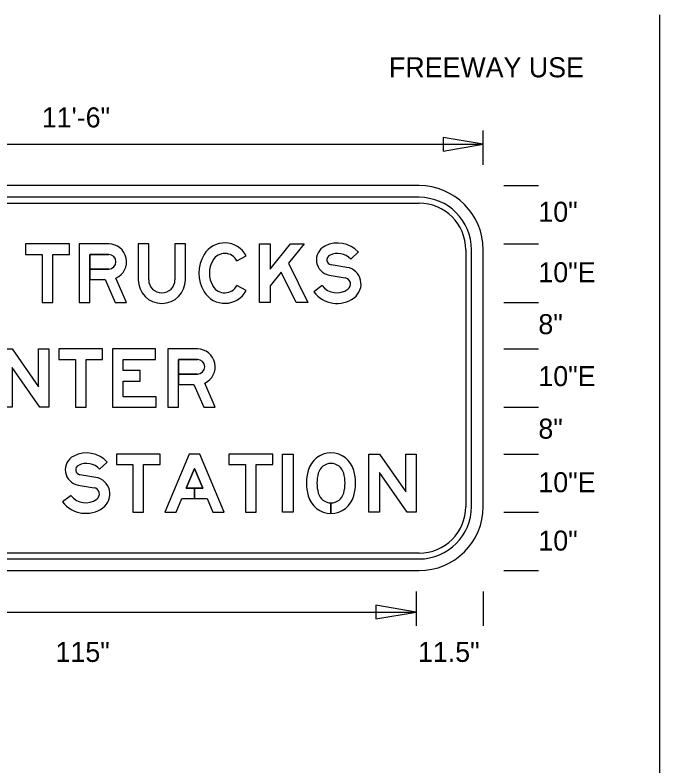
# Model space of a CAD drawing. Extents: x 0 to 770, y 0 to 495.
# Drawn here: x 80.1 to 192.8, y 363.9 to 495 of the extents above; entities that cross this region are included whole.
import ezdxf

# ---------------------------------------------------------------- set-up
doc = ezdxf.new("R2010")
doc.units = 0
for name, color, linetype in [('Dimension', 7, 'Continuous'), ('GSBWFill', 7, 'Continuous'), ('GSColorFill', 7, 'Continuous'), ('GSDims', 7, 'Continuous'), ('GSOutline', 7, 'Continuous'), ('SheetLines_dp', 7, 'Continuous'), ('TextStructures', 7, 'Continuous')]:
    doc.layers.add(name, color=color, linetype=linetype)

msp = doc.modelspace()

# ---------------------------------------------------------------- linework, layer by layer
at = {"layer": 'Dimension'}
for points in [[(161.91, 472.41), (154.9, 473.59), (154.9, 471.22)], [(150.19, 390.68), (143.17, 391.87), (143.17, 389.49)]]:
    msp.add_lwpolyline(points, close=True, dxfattribs=at)
at = {"layer": 'GSBWFill'}
for p, q in [((150.7, 465.18), (32.46, 465.18)), ((150.7, 463.14), (32.46, 463.14)), ((32.46, 462.12), (150.7, 462.12)), ((108.04, 454.99), (108.04, 448.74)), ((138.76, 452.34), (140.1, 453.59)), ((158.86, 453.97), (158.86, 409.12)), ((159.87, 409.12), (159.87, 453.97)), ((161.91, 409.12), (161.91, 453.97)), ((118.86, 452.06), (120.48, 452.92)), ((138.1, 450.9), (135.32, 451.37)), ((135.01, 449.56), (137.79, 449.09)), ((120.48, 446.86), (118.86, 447.72)), ((118.86, 447.72), (118.86, 447.72)), ((133.76, 447.72), (132.3, 446.6)), ((94.87, 415.64), (96.22, 416.89)), ((94.21, 414.2), (91.44, 414.67)), ((91.13, 412.86), (93.91, 412.39)), ((89.88, 411.03), (88.42, 409.91)), ((135.31, 407.92), (135.31, 409.76)), ((135.31, 409.76), (135.31, 407.92)), ((150.7, 400.96), (32.47, 400.96)), ((32.47, 399.95), (150.7, 399.95)), ((32.46, 397.91), (150.7, 397.91))]:
    msp.add_line(p, q, dxfattribs=at)
for points in [[(81.95, 453.15), (84.85, 453.15), (84.85, 444.79), (86.69, 444.79), (86.69, 453.15), (89.59, 453.15), (89.59, 454.99), (81.95, 454.99)], [(130.62, 454.99), (127.89, 451.62), (131.28, 444.79), (129.23, 444.79), (126.62, 450.06), (124.66, 447.65), (124.66, 444.79), (122.82, 444.79), (122.82, 454.99), (124.66, 454.99), (124.66, 450.56), (128.26, 454.99)], [(86.03, 436.64), (86.03, 426.45), (84.45, 426.45), (79.6, 433.43), (79.6, 426.45), (77.77, 426.45), (77.77, 436.64), (79.61, 436.64), (84.19, 430.03), (84.19, 436.64)], [(87.76, 434.81), (90.66, 434.81), (90.66, 426.45), (92.5, 426.45), (92.5, 434.81), (95.4, 434.81), (95.4, 436.64), (87.76, 436.64)], [(104.78, 428.28), (98.97, 428.28), (98.97, 431.02), (101.98, 431.02), (101.98, 432.86), (98.97, 432.86), (98.97, 434.81), (104.63, 434.81), (104.63, 436.64), (97.14, 436.64), (97.14, 426.45), (104.78, 426.45)], [(97.8, 416.46), (100.7, 416.46), (100.7, 408.1), (102.54, 408.1), (102.54, 416.46), (105.44, 416.46), (105.44, 418.29), (97.8, 418.29)], [(112.89, 412.33), (111.46, 412.33), (111.46, 410.5), (113.66, 410.5), (114.67, 408.1), (116.66, 408.1), (112.38, 418.29), (110.54, 418.29), (106.26, 408.1), (108.25, 408.1), (109.26, 410.5), (111.46, 410.5), (111.46, 412.33), (110.03, 412.33), (111.46, 415.74)], [(117.47, 416.46), (120.38, 416.46), (120.38, 408.1), (122.21, 408.1), (122.21, 416.46), (125.12, 416.46), (125.12, 418.29), (117.47, 418.29)], [(126.85, 408.1), (126.85, 418.29), (128.68, 418.29), (128.68, 408.1)], [(150.19, 418.29), (150.19, 408.1), (148.61, 408.1), (143.77, 415.08), (143.77, 408.1), (141.93, 408.1), (141.93, 418.29), (143.78, 418.29), (148.36, 411.69), (148.36, 418.29)]]:
    msp.add_lwpolyline(points, close=True, dxfattribs=at)
for points in [[(96.47, 454.99), (91.33, 454.99), (91.33, 444.79), (93.16, 444.79), (93.16, 453.15), (96.47, 453.15)], [(103.46, 448.74), (103.46, 454.99), (101.62, 454.99), (101.62, 448.74)], [(109.88, 448.74), (109.88, 454.99), (108.04, 454.99)], [(96.47, 450.6), (93.16, 450.6), (93.16, 448.77)], [(93.16, 448.77), (95.86, 448.77), (97.58, 444.79), (99.58, 444.79), (97.74, 449.04)], [(111.97, 436.64), (106.82, 436.64), (106.82, 426.45), (108.65, 426.45), (108.65, 434.81), (111.97, 434.81)], [(111.97, 432.26), (108.66, 432.26), (108.66, 430.42)], [(108.66, 430.42), (111.36, 430.42), (113.08, 426.45), (115.08, 426.45), (113.24, 430.69)]]:
    msp.add_lwpolyline(points, dxfattribs=at)
for centre, radius, start, end in [((150.7, 453.97), 11.21, 0, 90), ((150.7, 453.97), 9.17, 0, 90), ((150.7, 453.97), 8.15, 0, 90), ((136.48, 450.22), 4.94, 42.8759, 116.9123), ((135.46, 452.22), 2.7, 116.9123, 260.4087), ((135.46, 452.22), 0.866, 116.9123, 260.4087), ((136.48, 450.22), 3.11, 42.8759, 116.9123), ((137.6, 447.98), 2.96, 306.123, 80.4087), ((105.75, 448.74), 4.13, 180, 0), ((105.75, 448.74), 2.29, 180, 0), ((137.6, 447.98), 1.12, 306.123, 80.4087), ((136.34, 449.71), 3.26, 217.5895, 306.123), ((136.34, 449.71), 5.1, 217.5895, 306.123), ((150.7, 409.12), 9.17, 270, 0), ((150.7, 409.12), 8.15, 270, 0), ((150.7, 409.12), 11.21, 270, 0)]:
    msp.add_arc(centre, radius, start, end, dxfattribs=at)
for centre, major_axis, start_param, end_param in [((96.47, 451.88), (0, 3.11), 3.562504, 6.283185), ((116.74, 450.94), (0, 4.23), 5.201543, 7.308565), ((96.47, 451.88), (0, 1.27), 3.141593, 6.283185), ((118.47, 449.89), (0, 6.24), 1.025379, 2.116213), ((118.47, 449.89), (0, 4.41), 1.025379, 2.116213), ((116.74, 450.94), (0, 2.4), 5.201543, 7.308565), ((116.74, 448.85), (0, 2.4), 2.116213, 4.223235), ((116.74, 448.85), (0, 4.23), 2.116213, 4.223235), ((111.97, 433.53), (0, 3.11), 3.562504, 6.283185), ((111.97, 433.53), (0, 1.27), 3.141593, 6.283185), ((92.6, 413.53), (0, 4.94), 5.460714, 6.752893), ((135.31, 414.34), (0, 4.13), 4.973521, 7.592849), ((91.58, 415.53), (0, 2.7), 0.469708, 2.974193), ((92.6, 413.53), (0, 3.11), 5.460714, 6.752893), ((91.58, 415.53), (0, 0.866), 0.469708, 2.974193), ((135.31, 414.34), (0, 2.3), 4.973521, 7.592849), ((93.72, 411.29), (0, 2.96), 3.772058, 6.115786), ((139.59, 413.2), (0, 8.56), 1.309664, 1.831929), ((139.59, 413.2), (0, 6.73), 1.309664, 1.831929), ((131.03, 413.2), (0, 6.73), 4.451257, 4.973521), ((131.03, 413.2), (0, 8.56), 4.451257, 4.973521), ((93.72, 411.29), (0, 1.12), 3.772058, 6.115786), ((92.46, 413.02), (0, 3.26), 2.226857, 3.772058), ((135.31, 412.05), (0, 4.13), 1.831929, 3.141593), ((135.31, 412.05), (0, 2.3), 1.831929, 3.141593), ((135.31, 412.05), (0, 2.3), 3.141815, 4.451257), ((135.31, 412.05), (0, 4.13), 3.141716, 4.451257), ((92.46, 413.02), (0, 5.1), 2.226857, 3.772058)]:
    msp.add_ellipse(centre, major_axis=major_axis, ratio=0.999994, start_param=start_param, end_param=end_param, dxfattribs=at)
at = {"layer": 'GSColorFill'}
for p, q in [((108.04, 454.99), (108.04, 448.74)), ((138.76, 452.34), (140.1, 453.59)), ((118.86, 452.06), (120.48, 452.92)), ((138.1, 450.9), (135.32, 451.37)), ((135.01, 449.56), (137.79, 449.09)), ((120.48, 446.86), (118.86, 447.72)), ((118.86, 447.72), (118.86, 447.72)), ((133.76, 447.72), (132.3, 446.6)), ((94.87, 415.64), (96.22, 416.89)), ((94.21, 414.2), (91.44, 414.67)), ((91.13, 412.86), (93.91, 412.39)), ((89.88, 411.03), (88.42, 409.91)), ((135.31, 407.92), (135.31, 409.76)), ((135.31, 409.76), (135.31, 407.92))]:
    msp.add_line(p, q, dxfattribs=at)
for points in [[(81.95, 453.15), (84.85, 453.15), (84.85, 444.79), (86.69, 444.79), (86.69, 453.15), (89.59, 453.15), (89.59, 454.99), (81.95, 454.99)], [(130.62, 454.99), (127.89, 451.62), (131.28, 444.79), (129.23, 444.79), (126.62, 450.06), (124.66, 447.65), (124.66, 444.79), (122.82, 444.79), (122.82, 454.99), (124.66, 454.99), (124.66, 450.56), (128.26, 454.99)], [(86.03, 436.64), (86.03, 426.45), (84.45, 426.45), (79.6, 433.43), (79.6, 426.45), (77.77, 426.45), (77.77, 436.64), (79.61, 436.64), (84.19, 430.03), (84.19, 436.64)], [(87.76, 434.81), (90.66, 434.81), (90.66, 426.45), (92.5, 426.45), (92.5, 434.81), (95.4, 434.81), (95.4, 436.64), (87.76, 436.64)], [(104.78, 428.28), (98.97, 428.28), (98.97, 431.02), (101.98, 431.02), (101.98, 432.86), (98.97, 432.86), (98.97, 434.81), (104.63, 434.81), (104.63, 436.64), (97.14, 436.64), (97.14, 426.45), (104.78, 426.45)], [(97.8, 416.46), (100.7, 416.46), (100.7, 408.1), (102.54, 408.1), (102.54, 416.46), (105.44, 416.46), (105.44, 418.29), (97.8, 418.29)], [(112.89, 412.33), (111.46, 412.33), (111.46, 410.5), (113.66, 410.5), (114.67, 408.1), (116.66, 408.1), (112.38, 418.29), (110.54, 418.29), (106.26, 408.1), (108.25, 408.1), (109.26, 410.5), (111.46, 410.5), (111.46, 412.33), (110.03, 412.33), (111.46, 415.74)], [(117.47, 416.46), (120.38, 416.46), (120.38, 408.1), (122.21, 408.1), (122.21, 416.46), (125.12, 416.46), (125.12, 418.29), (117.47, 418.29)], [(126.85, 408.1), (126.85, 418.29), (128.68, 418.29), (128.68, 408.1)], [(150.19, 418.29), (150.19, 408.1), (148.61, 408.1), (143.77, 415.08), (143.77, 408.1), (141.93, 408.1), (141.93, 418.29), (143.78, 418.29), (148.36, 411.69), (148.36, 418.29)]]:
    msp.add_lwpolyline(points, close=True, dxfattribs=at)
for points in [[(96.47, 454.99), (91.33, 454.99), (91.33, 444.79), (93.16, 444.79), (93.16, 453.15), (96.47, 453.15)], [(103.46, 448.74), (103.46, 454.99), (101.62, 454.99), (101.62, 448.74)], [(109.88, 448.74), (109.88, 454.99), (108.04, 454.99)], [(96.47, 450.6), (93.16, 450.6), (93.16, 448.77)], [(93.16, 448.77), (95.86, 448.77), (97.58, 444.79), (99.58, 444.79), (97.74, 449.04)], [(111.97, 436.64), (106.82, 436.64), (106.82, 426.45), (108.65, 426.45), (108.65, 434.81), (111.97, 434.81)], [(111.97, 432.26), (108.66, 432.26), (108.66, 430.42)], [(108.66, 430.42), (111.36, 430.42), (113.08, 426.45), (115.08, 426.45), (113.24, 430.69)]]:
    msp.add_lwpolyline(points, dxfattribs=at)
for centre, radius, start, end in [((136.48, 450.22), 4.94, 42.8759, 116.9123), ((135.46, 452.22), 2.7, 116.9123, 260.4087), ((135.46, 452.22), 0.866, 116.9123, 260.4087), ((136.48, 450.22), 3.11, 42.8759, 116.9123), ((137.6, 447.98), 2.96, 306.123, 80.4087), ((105.75, 448.74), 4.13, 180, 0), ((105.75, 448.74), 2.29, 180, 0), ((137.6, 447.98), 1.12, 306.123, 80.4087), ((136.34, 449.71), 3.26, 217.5895, 306.123), ((136.34, 449.71), 5.1, 217.5895, 306.123)]:
    msp.add_arc(centre, radius, start, end, dxfattribs=at)
for centre, major_axis, start_param, end_param in [((96.47, 451.88), (0, 3.11), 3.562504, 6.283185), ((116.74, 450.94), (0, 4.23), 5.201543, 7.308565), ((96.47, 451.88), (0, 1.27), 3.141593, 6.283185), ((118.47, 449.89), (0, 6.24), 1.025379, 2.116213), ((118.47, 449.89), (0, 4.41), 1.025379, 2.116213), ((116.74, 450.94), (0, 2.4), 5.201543, 7.308565), ((116.74, 448.85), (0, 2.4), 2.116213, 4.223235), ((116.74, 448.85), (0, 4.23), 2.116213, 4.223235), ((111.97, 433.53), (0, 3.11), 3.562504, 6.283185), ((111.97, 433.53), (0, 1.27), 3.141593, 6.283185), ((92.6, 413.53), (0, 4.94), 5.460714, 6.752893), ((135.31, 414.34), (0, 4.13), 4.973521, 7.592849), ((91.58, 415.53), (0, 2.7), 0.469708, 2.974193), ((92.6, 413.53), (0, 3.11), 5.460714, 6.752893), ((91.58, 415.53), (0, 0.866), 0.469708, 2.974193), ((135.31, 414.34), (0, 2.3), 4.973521, 7.592849), ((93.72, 411.29), (0, 2.96), 3.772058, 6.115786), ((139.59, 413.2), (0, 8.56), 1.309664, 1.831929), ((139.59, 413.2), (0, 6.73), 1.309664, 1.831929), ((131.03, 413.2), (0, 6.73), 4.451257, 4.973521), ((131.03, 413.2), (0, 8.56), 4.451257, 4.973521), ((93.72, 411.29), (0, 1.12), 3.772058, 6.115786), ((92.46, 413.02), (0, 3.26), 2.226857, 3.772058), ((135.31, 412.05), (0, 4.13), 1.831929, 3.141593), ((135.31, 412.05), (0, 2.3), 1.831929, 3.141593), ((135.31, 412.05), (0, 2.3), 3.141815, 4.451257), ((135.31, 412.05), (0, 4.13), 3.141716, 4.451257), ((92.46, 413.02), (0, 5.1), 2.226857, 3.772058)]:
    msp.add_ellipse(centre, major_axis=major_axis, ratio=0.999994, start_param=start_param, end_param=end_param, dxfattribs=at)
at = {"layer": 'GSDims'}
for p, q in [((161.91, 468.79), (161.91, 474.81)), ((21.25, 472.41), (161.91, 472.41)), ((165.53, 465.18), (171.55, 465.18)), ((165.53, 454.99), (171.55, 454.99)), ((165.53, 454.99), (171.55, 454.99)), ((165.53, 444.79), (171.55, 444.79)), ((165.53, 444.79), (171.55, 444.79)), ((165.53, 436.64), (171.55, 436.64)), ((165.53, 436.64), (171.55, 436.64)), ((165.53, 426.45), (171.55, 426.45)), ((165.53, 426.45), (171.55, 426.45)), ((165.53, 418.29), (171.55, 418.29)), ((165.53, 418.29), (171.55, 418.29)), ((165.53, 408.1), (171.55, 408.1)), ((165.53, 408.1), (171.55, 408.1)), ((165.53, 397.91), (171.55, 397.91)), ((150.19, 394.29), (150.19, 388.27)), ((150.19, 394.29), (150.19, 388.27)), ((161.91, 394.29), (161.91, 388.27)), ((32.97, 390.68), (150.19, 390.68))]:
    msp.add_line(p, q, dxfattribs=at)
at = {"layer": 'GSOutline'}
for p, q in [((108.04, 454.99), (108.04, 448.74)), ((138.76, 452.34), (140.1, 453.59)), ((118.86, 452.06), (120.48, 452.92)), ((138.1, 450.9), (135.32, 451.37)), ((93.16, 450.6), (96.47, 450.6)), ((135.01, 449.56), (137.79, 449.09)), ((120.48, 446.86), (118.86, 447.72)), ((118.86, 447.72), (118.86, 447.72)), ((133.76, 447.72), (132.3, 446.6)), ((108.65, 432.26), (111.97, 432.26)), ((94.87, 415.64), (96.22, 416.89)), ((94.21, 414.2), (91.44, 414.67)), ((91.13, 412.86), (93.91, 412.39)), ((89.88, 411.03), (88.42, 409.91))]:
    msp.add_line(p, q, dxfattribs=at)
for points in [[(81.95, 453.15), (84.85, 453.15), (84.85, 444.79), (86.69, 444.79), (86.69, 453.15), (89.59, 453.15), (89.59, 454.99), (81.95, 454.99)], [(130.62, 454.99), (127.89, 451.62), (131.28, 444.79), (129.23, 444.79), (126.62, 450.06), (124.66, 447.65), (124.66, 444.79), (122.82, 444.79), (122.82, 454.99), (124.66, 454.99), (124.66, 450.56), (128.26, 454.99)], [(86.03, 436.64), (86.03, 426.45), (84.45, 426.45), (79.6, 433.43), (79.6, 426.45), (77.77, 426.45), (77.77, 436.64), (79.61, 436.64), (84.19, 430.03), (84.19, 436.64)], [(87.76, 434.81), (90.66, 434.81), (90.66, 426.45), (92.5, 426.45), (92.5, 434.81), (95.4, 434.81), (95.4, 436.64), (87.76, 436.64)], [(104.78, 428.28), (98.97, 428.28), (98.97, 431.02), (101.98, 431.02), (101.98, 432.86), (98.97, 432.86), (98.97, 434.81), (104.63, 434.81), (104.63, 436.64), (97.14, 436.64), (97.14, 426.45), (104.78, 426.45)], [(97.8, 416.46), (100.7, 416.46), (100.7, 408.1), (102.54, 408.1), (102.54, 416.46), (105.44, 416.46), (105.44, 418.29), (97.8, 418.29)], [(109.26, 410.5), (113.66, 410.5), (114.67, 408.1), (116.66, 408.1), (112.38, 418.29), (110.54, 418.29), (106.26, 408.1), (108.25, 408.1)], [(117.47, 416.46), (120.38, 416.46), (120.38, 408.1), (122.21, 408.1), (122.21, 416.46), (125.12, 416.46), (125.12, 418.29), (117.47, 418.29)], [(126.85, 408.1), (126.85, 418.29), (128.68, 418.29), (128.68, 408.1)], [(150.19, 418.29), (150.19, 408.1), (148.61, 408.1), (143.77, 415.08), (143.77, 408.1), (141.93, 408.1), (141.93, 418.29), (143.78, 418.29), (148.36, 411.69), (148.36, 418.29)], [(112.89, 412.33), (111.46, 415.74), (110.03, 412.33)]]:
    msp.add_lwpolyline(points, close=True, dxfattribs=at)
for points in [[(96.47, 454.99), (91.33, 454.99), (91.33, 444.79), (93.16, 444.79), (93.16, 448.77), (95.86, 448.77)], [(103.46, 448.74), (103.46, 454.99), (101.62, 454.99), (101.62, 448.74)], [(109.88, 448.74), (109.88, 454.99), (108.04, 454.99)], [(96.47, 453.15), (93.16, 453.15), (93.16, 450.6)], [(95.86, 448.77), (97.58, 444.79), (99.58, 444.79), (97.74, 449.04)], [(111.97, 436.64), (106.82, 436.64), (106.82, 426.45), (108.65, 426.45), (108.65, 430.42), (111.36, 430.42)], [(111.97, 434.81), (108.65, 434.81), (108.65, 432.26)], [(111.36, 430.42), (113.08, 426.45), (115.08, 426.45), (113.24, 430.69)]]:
    msp.add_lwpolyline(points, dxfattribs=at)
for centre, radius, start, end in [((136.48, 450.22), 4.94, 42.8759, 116.9123), ((135.46, 452.22), 2.7, 116.9123, 260.4087), ((135.46, 452.22), 0.866, 116.9123, 260.4087), ((136.48, 450.22), 3.11, 42.8759, 116.9123), ((137.6, 447.98), 2.96, 306.123, 80.4087), ((105.75, 448.74), 4.13, 180, 0), ((105.75, 448.74), 2.29, 180, 0), ((137.6, 447.98), 1.12, 306.123, 80.4087), ((136.34, 449.71), 3.26, 217.5895, 306.123), ((136.34, 449.71), 5.1, 217.5895, 306.123)]:
    msp.add_arc(centre, radius, start, end, dxfattribs=at)
for centre, major_axis, start_param, end_param in [((96.47, 451.88), (0, 3.11), 3.562504, 6.283185), ((116.74, 450.94), (0, 4.23), 5.201543, 7.308565), ((96.47, 451.88), (0, 1.27), 3.141593, 6.283185), ((118.47, 449.89), (0, 6.24), 1.025379, 2.116213), ((118.47, 449.89), (0, 4.41), 1.025379, 2.116213), ((116.74, 450.94), (0, 2.4), 5.201543, 7.308565), ((116.74, 448.85), (0, 2.4), 2.116213, 4.223235), ((116.74, 448.85), (0, 4.23), 2.116213, 4.223235), ((111.97, 433.53), (0, 3.11), 3.562504, 6.283185), ((111.97, 433.53), (0, 1.27), 3.141593, 6.283185), ((92.6, 413.53), (0, 4.94), 5.460714, 6.752893), ((135.31, 414.34), (0, 4.13), 4.973521, 7.592849), ((91.58, 415.53), (0, 2.7), 0.469708, 2.974193), ((92.6, 413.53), (0, 3.11), 5.460714, 6.752893), ((91.58, 415.53), (0, 0.866), 0.469708, 2.974193), ((135.31, 414.34), (0, 2.3), 4.973521, 7.592849), ((93.72, 411.29), (0, 2.96), 3.772058, 6.115786), ((139.59, 413.2), (0, 8.56), 1.309664, 1.831929), ((139.59, 413.2), (0, 6.73), 1.309664, 1.831929), ((131.03, 413.2), (0, 6.73), 4.451257, 4.973521), ((131.03, 413.2), (0, 8.56), 4.451257, 4.973521), ((93.72, 411.29), (0, 1.12), 3.772058, 6.115786), ((92.46, 413.02), (0, 3.26), 2.226857, 3.772058), ((135.31, 412.05), (0, 4.13), 1.831929, 4.451257), ((135.31, 412.05), (0, 2.3), 1.831929, 4.451257), ((92.46, 413.02), (0, 5.1), 2.226857, 3.772058)]:
    msp.add_ellipse(centre, major_axis=major_axis, ratio=0.999994, start_param=start_param, end_param=end_param, dxfattribs=at)
at = {"layer": 'SheetLines_dp'}
msp.add_line((192.8, 0), (192.8, 495), dxfattribs=at)

# ---------------------------------------------------------------- texts
at = {"layer": 'TextStructures'}
for s, p in [('FREEWAY USE', (145.44, 484.11)), ('11\'-6"', (84.78, 475.36)), ('10"', (171.55, 458.87)), ('10"E', (171.55, 448.3)), ('8"', (171.55, 439.23)), ('10"E', (171.55, 430.15)), ('8"', (171.55, 420.97)), ('10"E', (171.55, 411.61)), ('10"', (171.55, 401.41)), ('115"', (87.18, 381.96)), ('11.5"', (150.51, 381.96))]:
    msp.add_text(s, height=3.5, dxfattribs=at).set_placement(p)

doc.saveas('drawing.dxf')
